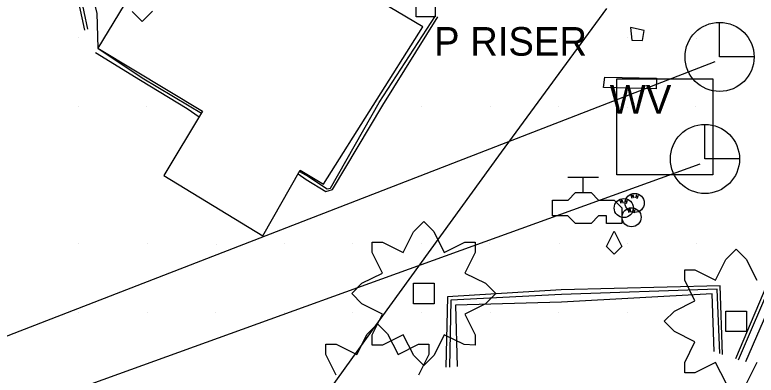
# Model space of a CAD drawing. Extents: x 1602514 to 1609837, y 863887 to 871157.
# Drawn here: x 1604716.3 to 1604878.4, y 866692.7 to 866771.5 of the extents above; entities that cross this region are included whole.
import ezdxf

# ---------------------------------------------------------------- set-up
doc = ezdxf.new("R2010")
doc.units = 0
for name, color, linetype in [('Environmental-New trees', 7, 'Continuous'), ('Survey-Buildings', 7, 'Continuous'), ('Survey-Curbs', 7, 'Continuous'), ('Survey-Edge of pavement', 7, 'Continuous'), ('Survey-Signs', 7, 'Continuous'), ('Survey-Spot dirt', 7, 'Continuous'), ('Text General Notes', 7, 'Continuous'), ('USER-Air conditioner', 7, 'Continuous'), ('USER-Landscape-Lighting', 7, 'Continuous'), ('USER-Manhole lid', 7, 'Continuous'), ('Utility-Pole', 7, 'Continuous'), ('Utility-Water', 7, 'Continuous')]:
    doc.layers.add(name, color=color, linetype=linetype)

msp = doc.modelspace()

# ---------------------------------------------------------------- linework, layer by layer
at = {"layer": 'Environmental-New trees'}
for points in [[(1604746.38, 866772.26), (1604744.13, 866770.01), (1604741.93, 866772.2)], [(1604746.38, 866772.26), (1604744.13, 866770.01), (1604741.93, 866772.2)], [(1604878.5, 866695.46), (1604876.25, 866690.96), (1604874, 866688.71), (1604871.81, 866690.9), (1604869.5, 866695.46), (1604865, 866693.21), (1604862.75, 866693.21), (1604862.75, 866695.46), (1604865, 866699.96), (1604860.5, 866702.21), (1604858.25, 866704.46), (1604860.5, 866706.71), (1604865, 866708.96), (1604862.75, 866713.46), (1604862.75, 866715.71), (1604865, 866715.71), (1604869.5, 866713.46), (1604871.75, 866717.96), (1604874, 866720.21), (1604876.19, 866718.02), (1604878.5, 866713.46)], [(1604878.5, 866695.46), (1604876.25, 866690.96), (1604874, 866688.71), (1604871.81, 866690.9), (1604869.5, 866695.46), (1604865, 866693.21), (1604862.75, 866693.21), (1604862.75, 866695.46), (1604865, 866699.96), (1604860.5, 866702.21), (1604858.25, 866704.46), (1604860.5, 866706.71), (1604865, 866708.96), (1604862.75, 866713.46), (1604862.75, 866715.71), (1604865, 866715.71), (1604869.5, 866713.46), (1604871.75, 866717.96), (1604874, 866720.21), (1604876.19, 866718.02), (1604878.5, 866713.46)], [(1604786.55, 866692.67), (1604784.3, 866697.17), (1604784.3, 866699.42), (1604786.55, 866699.42), (1604791.05, 866697.17), (1604793.3, 866701.67), (1604795.56, 866703.92), (1604797.75, 866701.73), (1604800.06, 866697.17), (1604804.56, 866699.42), (1604806.81, 866699.42), (1604806.81, 866697.17), (1604804.56, 866692.67)], [(1604786.55, 866692.67), (1604784.3, 866697.17), (1604784.3, 866699.42), (1604786.55, 866699.42), (1604791.05, 866697.17), (1604793.3, 866701.67), (1604795.56, 866703.92), (1604797.75, 866701.73), (1604800.06, 866697.17), (1604804.56, 866699.42), (1604806.81, 866699.42), (1604806.81, 866697.17), (1604804.56, 866692.67)]]:
    msp.add_lwpolyline(points, dxfattribs=at)
for points in [[(1604794.43, 866721.78), (1604796.68, 866721.78), (1604801.18, 866719.53), (1604803.43, 866724.03), (1604805.68, 866726.28), (1604807.87, 866724.08), (1604810.18, 866719.53), (1604814.68, 866721.78), (1604816.93, 866721.78), (1604816.93, 866719.53), (1604814.68, 866715.02), (1604819.18, 866712.77), (1604821.43, 866710.52), (1604819.18, 866708.27), (1604814.68, 866706.02), (1604816.93, 866701.52), (1604816.93, 866699.27), (1604814.51, 866699.36), (1604810.18, 866701.52), (1604807.93, 866697.02), (1604805.68, 866694.77), (1604803.49, 866696.96), (1604801.18, 866701.52), (1604796.68, 866699.27), (1604794.43, 866699.27), (1604794.43, 866701.52), (1604796.68, 866706.02), (1604792.18, 866708.27), (1604789.93, 866710.52), (1604792.18, 866712.77), (1604796.68, 866715.02), (1604794.43, 866719.53)], [(1604794.43, 866721.78), (1604796.68, 866721.78), (1604801.18, 866719.53), (1604803.43, 866724.03), (1604805.68, 866726.28), (1604807.87, 866724.08), (1604810.18, 866719.53), (1604814.68, 866721.78), (1604816.93, 866721.78), (1604816.93, 866719.53), (1604814.68, 866715.02), (1604819.18, 866712.77), (1604821.43, 866710.52), (1604819.18, 866708.27), (1604814.68, 866706.02), (1604816.93, 866701.52), (1604816.93, 866699.27), (1604814.51, 866699.36), (1604810.18, 866701.52), (1604807.93, 866697.02), (1604805.68, 866694.77), (1604803.49, 866696.96), (1604801.18, 866701.52), (1604796.68, 866699.27), (1604794.43, 866699.27), (1604794.43, 866701.52), (1604796.68, 866706.02), (1604792.18, 866708.27), (1604789.93, 866710.52), (1604792.18, 866712.77), (1604796.68, 866715.02), (1604794.43, 866719.53)], [(1604807.93, 866712.77), (1604807.93, 866708.27), (1604803.43, 866708.27), (1604803.43, 866712.77)], [(1604807.93, 866712.77), (1604807.93, 866708.27), (1604803.43, 866708.27), (1604803.43, 866712.77)], [(1604876.25, 866706.71), (1604876.25, 866702.21), (1604871.75, 866702.21), (1604871.75, 866706.71)], [(1604876.25, 866706.71), (1604876.25, 866702.21), (1604871.75, 866702.21), (1604871.75, 866706.71)]]:
    msp.add_lwpolyline(points, close=True, dxfattribs=at)
at = {"layer": 'Survey-Buildings'}
msp.add_lwpolyline([(1604805.45, 866768.86), (1604755.28, 866798.65), (1604748.21, 866786.97), (1604734.44, 866764.18), (1604757.31, 866750.39), (1604748.83, 866736.32), (1604770.5, 866723.16), (1604778.69, 866737.51), (1604783.78, 866734.44)], close=True, dxfattribs=at)
msp.add_lwpolyline([(1604805.45, 866768.86), (1604755.28, 866798.65), (1604748.21, 866786.97), (1604734.44, 866764.18), (1604757.31, 866750.39), (1604748.83, 866736.32), (1604770.5, 866723.16), (1604778.69, 866737.51), (1604783.78, 866734.44)], close=True, dxfattribs=at)
at = {"layer": 'Survey-Curbs'}
msp.add_line((1604874.55, 866696.06), (1604891.46, 866735.7), dxfattribs=at)
msp.add_line((1604874.55, 866696.06), (1604891.46, 866735.7), dxfattribs=at)
for points in [[(1604721.28, 866818.55), (1604726.56, 866794.96), (1604732.14, 866768.32)], [(1604721.28, 866818.55), (1604726.56, 866794.96), (1604732.14, 866768.32)], [(1604778.52, 866737.21), (1604780.45, 866736.16), (1604784.56, 866733.44), (1604785.3, 866733.56), (1604795.92, 866752.28), (1604808.26, 866771.3)], [(1604778.52, 866737.21), (1604780.45, 866736.16), (1604784.56, 866733.44), (1604785.3, 866733.56), (1604795.92, 866752.28), (1604808.26, 866771.3)], [(1604734.44, 866764.18), (1604744.09, 866757.73), (1604754.35, 866751.61), (1604757.05, 866749.97)], [(1604734.44, 866764.18), (1604744.09, 866757.73), (1604754.35, 866751.61), (1604757.05, 866749.97)], [(1604901.18, 866761.84), (1604890.74, 866736.18), (1604873.88, 866696.28)], [(1604901.18, 866761.84), (1604890.74, 866736.18), (1604873.88, 866696.28)], [(1604871, 866697.22), (1604870.5, 866712.23), (1604835.74, 866711.33), (1604810.89, 866709.78), (1604810.48, 866694.4)], [(1604871, 866697.22), (1604870.5, 866712.23), (1604835.74, 866711.33), (1604810.89, 866709.78), (1604810.48, 866694.4)], [(1604870.45, 866697.4), (1604869.83, 866711.52), (1604835.78, 866710.29), (1604811.6, 866709.07), (1604811.32, 866694.45)], [(1604870.45, 866697.4), (1604869.83, 866711.52), (1604835.78, 866710.29), (1604811.6, 866709.07), (1604811.32, 866694.45)]]:
    msp.add_lwpolyline(points, dxfattribs=at)
at = {"layer": 'Survey-Edge of pavement'}
msp.add_line((1604778.22, 866736.69), (1604779.97, 866735.44), dxfattribs=at)
msp.add_line((1604778.22, 866736.69), (1604779.97, 866735.44), dxfattribs=at)
for points in [[(1604720.7, 866818.01), (1604725.75, 866794.79), (1604731.49, 866768.13)], [(1604720.7, 866818.01), (1604725.75, 866794.79), (1604731.49, 866768.13)], [(1604726.22, 866806.45), (1604729.05, 866792.36), (1604734.23, 866771.84), (1604734.44, 866764.18)], [(1604726.22, 866806.45), (1604729.05, 866792.36), (1604734.23, 866771.84), (1604734.44, 866764.18)], [(1604845.65, 866772.91), (1604822.6, 866741.47), (1604796.09, 866704.84), (1604775.38, 866676.02), (1604745.42, 866684.38), (1604717.27, 866690.11)], [(1604845.65, 866772.91), (1604822.6, 866741.47), (1604796.09, 866704.84), (1604775.38, 866676.02), (1604745.42, 866684.38), (1604717.27, 866690.11)], [(1604779.97, 866735.44), (1604784.28, 866732.82), (1604785.74, 866733.3), (1604796.77, 866751.75), (1604808.73, 866771.02)], [(1604779.97, 866735.44), (1604784.28, 866732.82), (1604785.74, 866733.3), (1604796.77, 866751.75), (1604808.73, 866771.02)], [(1604733.87, 866763.25), (1604743.74, 866757.19), (1604753.95, 866750.99), (1604756.57, 866749.17)], [(1604733.87, 866763.25), (1604743.74, 866757.19), (1604753.95, 866750.99), (1604756.57, 866749.17)], [(1604906.18, 866712.72), (1604890.05, 866727.84), (1604876.01, 866695.58)], [(1604906.18, 866712.72), (1604890.05, 866727.84), (1604876.01, 866695.58)], [(1604869.18, 866697.82), (1604868.79, 866710.43), (1604835.83, 866708.65), (1604812.64, 866708.02), (1604812.99, 866694.55)], [(1604869.18, 866697.82), (1604868.79, 866710.43), (1604835.83, 866708.65), (1604812.64, 866708.02), (1604812.99, 866694.55)]]:
    msp.add_lwpolyline(points, dxfattribs=at)
at = {"layer": 'Survey-Signs'}
msp.add_lwpolyline([(1604845.29, 866757.83), (1604856.59, 866757.61), (1604856.54, 866755.31), (1604845.02, 866755.62)], close=True, dxfattribs=at)
msp.add_lwpolyline([(1604845.29, 866757.83), (1604856.59, 866757.61), (1604856.54, 866755.31), (1604845.02, 866755.62)], close=True, dxfattribs=at)
at = {"layer": 'Survey-Spot dirt'}
for p, q in [((1604730.24, 866766.45), (1604730.24, 866766.45)), ((1604730.24, 866766.45), (1604730.24, 866766.45)), ((1604820.15, 866766.43), (1604820.15, 866766.43)), ((1604820.15, 866766.43), (1604820.15, 866766.43)), ((1604835.31, 866766.38), (1604835.31, 866766.38)), ((1604835.31, 866766.38), (1604835.31, 866766.38)), ((1604850.18, 866766.55), (1604850.18, 866766.55)), ((1604850.18, 866766.55), (1604850.18, 866766.55)), ((1604865.31, 866766.37), (1604865.31, 866766.37)), ((1604865.31, 866766.37), (1604865.31, 866766.37)), ((1604730.19, 866751.48), (1604730.19, 866751.48)), ((1604730.19, 866751.48), (1604730.19, 866751.48)), ((1604745.15, 866751.47), (1604745.15, 866751.47)), ((1604745.15, 866751.47), (1604745.15, 866751.47)), ((1604805.22, 866751.45), (1604805.22, 866751.45)), ((1604805.22, 866751.45), (1604805.22, 866751.45)), ((1604835.15, 866751.5), (1604835.15, 866751.5)), ((1604835.15, 866751.5), (1604835.15, 866751.5)), ((1604820.18, 866751.37), (1604820.18, 866751.37)), ((1604820.18, 866751.37), (1604820.18, 866751.37)), ((1604850.27, 866751.32), (1604850.27, 866751.32)), ((1604850.27, 866751.32), (1604850.27, 866751.32)), ((1604865.21, 866751.42), (1604865.21, 866751.42)), ((1604865.21, 866751.42), (1604865.21, 866751.42)), ((1604730.23, 866721.42), (1604730.23, 866721.42)), ((1604730.23, 866721.42), (1604730.23, 866721.42)), ((1604745.18, 866721.38), (1604745.18, 866721.38)), ((1604745.18, 866721.38), (1604745.18, 866721.38)), ((1604760.27, 866721.35), (1604760.27, 866721.35)), ((1604760.27, 866721.35), (1604760.27, 866721.35)), ((1604775.21, 866721.45), (1604775.21, 866721.45)), ((1604775.21, 866721.45), (1604775.21, 866721.45)), ((1604790.18, 866721.48), (1604790.18, 866721.48)), ((1604790.18, 866721.48), (1604790.18, 866721.48)), ((1604805.19, 866721.51), (1604805.19, 866721.51)), ((1604805.19, 866721.51), (1604805.19, 866721.51)), ((1604820.15, 866721.47), (1604820.15, 866721.47)), ((1604820.15, 866721.47), (1604820.15, 866721.47)), ((1604835.3, 866721.42), (1604835.3, 866721.42)), ((1604835.3, 866721.42), (1604835.3, 866721.42)), ((1604850.18, 866721.41), (1604850.18, 866721.41)), ((1604850.18, 866721.41), (1604850.18, 866721.41)), ((1604865.26, 866721.41), (1604865.26, 866721.41)), ((1604865.26, 866721.41), (1604865.26, 866721.41)), ((1604730.22, 866706.45), (1604730.22, 866706.45)), ((1604730.22, 866706.45), (1604730.22, 866706.45)), ((1604745.24, 866706.38), (1604745.24, 866706.38)), ((1604745.24, 866706.38), (1604745.24, 866706.38)), ((1604760.21, 866706.41), (1604760.21, 866706.41)), ((1604760.21, 866706.41), (1604760.21, 866706.41)), ((1604775.2, 866706.42), (1604775.2, 866706.42)), ((1604775.2, 866706.42), (1604775.2, 866706.42)), ((1604790.17, 866706.37), (1604790.17, 866706.37)), ((1604790.17, 866706.37), (1604790.17, 866706.37)), ((1604805.24, 866706.46), (1604805.24, 866706.46)), ((1604805.24, 866706.46), (1604805.24, 866706.46)), ((1604820.2, 866706.42), (1604820.2, 866706.42)), ((1604820.2, 866706.42), (1604820.2, 866706.42)), ((1604835.19, 866706.4), (1604835.19, 866706.4)), ((1604835.19, 866706.4), (1604835.19, 866706.4)), ((1604850.24, 866706.37), (1604850.24, 866706.37)), ((1604850.24, 866706.37), (1604850.24, 866706.37))]:
    msp.add_line(p, q, dxfattribs=at)
at = {"layer": 'Text General Notes'}
msp.add_lwpolyline([(1604869.31, 866761.21), (1604065.19, 866449.51), (1604866.11, 866738.89)], dxfattribs=at)
msp.add_lwpolyline([(1604869.31, 866761.21), (1604065.19, 866449.51), (1604866.11, 866738.89)], dxfattribs=at)
at = {"layer": 'USER-Air conditioner'}
msp.add_lwpolyline([(1604804.04, 866771.08), (1604804.04, 866775.22), (1604808.17, 866775.22), (1604808.17, 866771.08)], close=True, dxfattribs=at)
msp.add_lwpolyline([(1604804.04, 866771.08), (1604804.04, 866775.22), (1604808.17, 866775.22), (1604808.17, 866771.08)], close=True, dxfattribs=at)
at = {"layer": 'USER-Landscape-Lighting'}
msp.add_lwpolyline([(1604853.53, 866765.9), (1604853.91, 866768.04), (1604850.9, 866768.69), (1604851.22, 866765.96)], close=True, dxfattribs=at)
msp.add_lwpolyline([(1604853.53, 866765.9), (1604853.91, 866768.04), (1604850.9, 866768.69), (1604851.22, 866765.96)], close=True, dxfattribs=at)
at = {"layer": 'USER-Manhole lid'}
for p, q in [((1604851.27, 866731.3), (1604851.02, 866732.02)), ((1604851.02, 866732.02), (1604851.37, 866731.61)), ((1604851.27, 866731.3), (1604851.02, 866732.02)), ((1604851.02, 866732.02), (1604851.37, 866731.61)), ((1604851.37, 866731.61), (1604851.4, 866732.15)), ((1604851.37, 866731.61), (1604851.4, 866732.15)), ((1604851.4, 866732.15), (1604851.65, 866731.43)), ((1604851.4, 866732.15), (1604851.65, 866731.43)), ((1604852.03, 866731.44), (1604852.25, 866732.17)), ((1604852.03, 866731.44), (1604852.25, 866732.17)), ((1604852.39, 866731.32), (1604852.62, 866732.05)), ((1604852.39, 866731.32), (1604852.62, 866732.05)), ((1604848.89, 866730.19), (1604848.64, 866730.91)), ((1604848.64, 866730.91), (1604848.99, 866730.5)), ((1604848.89, 866730.19), (1604848.64, 866730.91)), ((1604848.64, 866730.91), (1604848.99, 866730.5)), ((1604848.99, 866730.5), (1604849.02, 866731.04)), ((1604848.99, 866730.5), (1604849.02, 866731.04)), ((1604849.02, 866731.04), (1604849.27, 866730.32)), ((1604849.02, 866731.04), (1604849.27, 866730.32)), ((1604849.65, 866730.33), (1604849.88, 866731.06)), ((1604849.65, 866730.33), (1604849.88, 866731.06)), ((1604850.13, 866730.59), (1604849.77, 866730.71)), ((1604850.13, 866730.59), (1604849.77, 866730.71)), ((1604850.01, 866730.21), (1604850.24, 866730.94)), ((1604850.01, 866730.21), (1604850.24, 866730.94)), ((1604852.51, 866731.7), (1604852.14, 866731.82)), ((1604852.51, 866731.7), (1604852.14, 866731.82)), ((1604850.6, 866728.18), (1604850.35, 866728.9)), ((1604850.35, 866728.9), (1604850.7, 866728.49)), ((1604850.6, 866728.18), (1604850.35, 866728.9)), ((1604850.35, 866728.9), (1604850.7, 866728.49)), ((1604850.7, 866728.49), (1604850.72, 866729.03)), ((1604850.7, 866728.49), (1604850.72, 866729.03)), ((1604850.72, 866729.03), (1604850.97, 866728.3)), ((1604850.72, 866729.03), (1604850.97, 866728.3)), ((1604851.35, 866728.31), (1604851.58, 866729.05)), ((1604851.35, 866728.31), (1604851.58, 866729.05)), ((1604851.72, 866728.2), (1604851.94, 866728.93)), ((1604851.72, 866728.2), (1604851.94, 866728.93)), ((1604851.83, 866728.58), (1604851.47, 866728.69)), ((1604851.83, 866728.58), (1604851.47, 866728.69))]:
    msp.add_line(p, q, dxfattribs=at)
for centre in [(1604851.81, 866730.34), (1604851.81, 866730.34), (1604849.43, 866729.23), (1604849.43, 866729.23), (1604851.13, 866727.21), (1604851.13, 866727.21)]:
    msp.add_circle(centre, 2.09, dxfattribs=at)
at = {"layer": 'Utility-Pole'}
msp.add_lwpolyline([(1604847.89, 866757.51), (1604868.9, 866757.51), (1604868.9, 866736.5), (1604847.89, 866736.5)], close=True, dxfattribs=at)
msp.add_lwpolyline([(1604847.89, 866757.51), (1604868.9, 866757.51), (1604868.9, 866736.5), (1604847.89, 866736.5)], close=True, dxfattribs=at)
at = {"layer": 'Utility-Water'}
for p, q in [((1604870.38, 866762.28), (1604870.38, 866769.84)), ((1604870.38, 866762.28), (1604870.38, 866769.84)), ((1604870.38, 866762.28), (1604870.38, 866762.28)), ((1604877.94, 866762.28), (1604870.38, 866762.28)), ((1604870.38, 866762.28), (1604870.38, 866762.28)), ((1604877.94, 866762.28), (1604870.38, 866762.28)), ((1604867.18, 866739.96), (1604867.18, 866747.52)), ((1604867.18, 866739.96), (1604867.18, 866747.52)), ((1604867.18, 866739.96), (1604867.18, 866739.96)), ((1604874.73, 866739.96), (1604867.18, 866739.96)), ((1604867.18, 866739.96), (1604867.18, 866739.96)), ((1604874.73, 866739.96), (1604867.18, 866739.96)), ((1604837.22, 866735.96), (1604843.93, 866735.96)), ((1604837.22, 866735.96), (1604843.93, 866735.96)), ((1604840.57, 866732.64), (1604840.57, 866735.94)), ((1604840.57, 866732.64), (1604840.57, 866735.94))]:
    msp.add_line(p, q, dxfattribs=at)
for points in [[(1604833.86, 866730.92), (1604837.27, 866730.97), (1604838.89, 866732.6), (1604842.26, 866732.6), (1604843.93, 866730.92), (1604847.29, 866730.92), (1604848.98, 866729.24), (1604848.98, 866725.88), (1604845.62, 866725.88), (1604845.62, 866727.56), (1604843.93, 866727.56), (1604842.26, 866725.88), (1604838.89, 866725.88), (1604837.22, 866727.56), (1604833.86, 866727.56)], [(1604833.86, 866730.92), (1604837.27, 866730.97), (1604838.89, 866732.6), (1604842.26, 866732.6), (1604843.93, 866730.92), (1604847.29, 866730.92), (1604848.98, 866729.24), (1604848.98, 866725.88), (1604845.62, 866725.88), (1604845.62, 866727.56), (1604843.93, 866727.56), (1604842.26, 866725.88), (1604838.89, 866725.88), (1604837.22, 866727.56), (1604833.86, 866727.56)], [(1604847.29, 866724.2), (1604848.98, 866720.84), (1604847.29, 866719.16), (1604845.62, 866720.84)], [(1604847.29, 866724.2), (1604848.98, 866720.84), (1604847.29, 866719.16), (1604845.62, 866720.84)]]:
    msp.add_lwpolyline(points, close=True, dxfattribs=at)
for centre in [(1604870.38, 866762.28), (1604870.38, 866762.28), (1604867.18, 866739.96), (1604867.18, 866739.96)]:
    msp.add_circle(centre, 7.56, dxfattribs=at)

# ---------------------------------------------------------------- texts
at = {"layer": 'Utility-Pole'}
msp.add_text('P RISER', height=6.251, dxfattribs=at).set_placement((1604807.94, 866762.56))
msp.add_text('P RISER', height=6.251, dxfattribs=at).set_placement((1604807.94, 866762.56))
at = {"layer": 'Utility-Water'}
msp.add_text('WV', height=6.251, dxfattribs=at).set_placement((1604846.36, 866749.86))
msp.add_text('WV', height=6.251, dxfattribs=at).set_placement((1604846.36, 866749.86))

doc.saveas('drawing.dxf')
